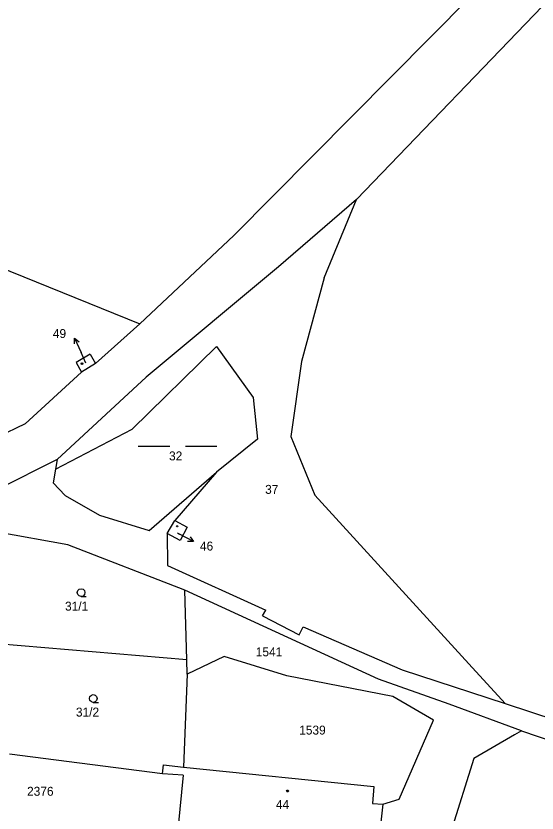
# Model space of a CAD drawing. Extents: x -852001 to -842497, y -1063614 to -1052182.
# Drawn here: x -850582.4 to -850483.1, y -1053481.6 to -1053329.6 of the extents above; entities that cross this region are included whole.
import ezdxf

# ---------------------------------------------------------------- set-up
doc = ezdxf.new("R2010")
doc.units = 0
for name, color, linetype in [('Default', 7, 'Continuous'), ('KN_HRANICE', 7, 'Continuous'), ('KN_KULTURY', 7, 'Continuous'), ('KN_PARCELY', 7, 'Continuous')]:
    doc.layers.add(name, color=color, linetype=linetype)

# ---------------------------------------------------------------- blocks, each defined once
blk = doc.blocks.new('304')
at = {"layer": 'Default'}
blk.add_lwpolyline([(0, 0), (-0.38, 0.1), (-0.65, 0.37), (-0.75, 0.74), (-0.65, 1.11), (-0.38, 1.38), (-0.01, 1.48), (0.36, 1.38), (0.63, 1.11), (0.73, 0.73), (0.63, 0.35), (0.36, 0.08), (-0.02, -0.02), (0.98, -0.02)], dxfattribs=at)
blk = doc.blocks.new('803')
at = {"layer": 'Default'}
for p, q in [((-7.5, 0), (-1.5, 0)), ((1.5, 0), (7.5, 0))]:
    blk.add_line(p, q, dxfattribs=at)
blk = doc.blocks.new('10292')
at = {"layer": 'Default'}
blk.add_line((0, 3), (0, 0), dxfattribs=at)
blk.add_lwpolyline([(-0.5, 2), (0, 3), (0.5, 2)], dxfattribs=at)
blk = doc.blocks.new('402')
at = {"layer": 'Default'}
blk.add_lwpolyline([(0.09, 0.15), (0.18, 0), (0.09, -0.15), (-0.09, -0.15), (-0.18, 0), (-0.09, 0.15), (0.09, 0.15)], dxfattribs=at)

msp = doc.modelspace()

# ---------------------------------------------------------------- linework, layer by layer
at = {"layer": 'KN_HRANICE'}
for p, q in [((-850422.36, -1053251.92), (-850540.88, -1053371.46)), ((-850471.08, -1053316.39), (-850517.5, -1053364.63)), ((-850517.5, -1053364.63), (-850532.35, -1053377.48)), ((-850523.63, -1053379.54), (-850517.5, -1053364.63)), ((-850540.88, -1053371.46), (-850558.84, -1053388.31)), ((-850593.21, -1053374.4), (-850558.84, -1053388.31)), ((-850532.35, -1053377.48), (-850557.63, -1053398.49)), ((-850523.63, -1053379.54), (-850527.95, -1053395.53)), ((-850558.84, -1053388.31), (-850567.28, -1053395.9)), ((-850560.27, -1053408.43), (-850544.19, -1053392.62)), ((-850544.19, -1053392.62), (-850537.17, -1053402.39)), ((-850568.31, -1053394.11), (-850570.95, -1053395.69)), ((-850568.31, -1053394.11), (-850567.28, -1053395.9)), ((-850570.95, -1053395.69), (-850569.94, -1053397.53)), ((-850567.28, -1053395.9), (-850569.94, -1053397.53)), ((-850527.95, -1053395.53), (-850530.04, -1053409.8)), ((-850569.94, -1053397.53), (-850580.7, -1053407.38)), ((-850557.63, -1053398.49), (-850574.57, -1053414.22)), ((-850537.17, -1053402.39), (-850536.37, -1053410.3)), ((-850580.7, -1053407.38), (-850599.94, -1053416.73)), ((-850574.9, -1053416.03), (-850560.27, -1053408.43)), ((-850536.37, -1053410.3), (-850544.21, -1053416.61)), ((-850530.04, -1053409.8), (-850525.46, -1053421.02)), ((-850574.57, -1053414.22), (-850604.96, -1053429.4)), ((-850574.57, -1053414.22), (-850574.9, -1053416.03)), ((-850574.9, -1053416.03), (-850575.37, -1053418.66)), ((-850557.06, -1053427.7), (-850544.21, -1053416.61)), ((-850544.21, -1053416.61), (-850552.11, -1053425.85)), ((-850575.37, -1053418.66), (-850573.02, -1053421.04)), ((-850573.02, -1053421.04), (-850566.48, -1053424.79)), ((-850525.46, -1053421.02), (-850496.05, -1053453.17)), ((-850566.48, -1053424.79), (-850557.06, -1053427.7)), ((-850572.57, -1053430.44), (-850592.25, -1053426.9)), ((-850553.62, -1053428.28), (-850552.11, -1053425.85)), ((-850552.11, -1053425.85), (-850549.78, -1053427.12)), ((-850549.78, -1053427.12), (-850551.12, -1053429.62)), ((-850551.12, -1053429.62), (-850553.62, -1053428.28)), ((-850553.62, -1053428.28), (-850553.56, -1053434.38)), ((-850550.25, -1053439.12), (-850572.57, -1053430.44)), ((-850553.56, -1053434.38), (-850534.81, -1053442.92)), ((-850513.32, -1053456.08), (-850550.25, -1053439.12)), ((-850549.87, -1053452.39), (-850550.25, -1053439.12)), ((-850535.39, -1053444.01), (-850534.81, -1053442.92)), ((-850535.39, -1053444.01), (-850528.4, -1053447.62)), ((-850528.4, -1053447.62), (-850527.68, -1053446.11)), ((-850527.68, -1053446.11), (-850508.76, -1053454.28)), ((-850549.87, -1053452.39), (-850589.27, -1053449.03)), ((-850549.8, -1053455.11), (-850549.87, -1053452.39)), ((-850542.75, -1053451.78), (-850549.8, -1053455.11)), ((-850530.79, -1053455.44), (-850542.75, -1053451.78)), ((-850508.76, -1053454.28), (-850489.13, -1053460.73)), ((-850496.05, -1053453.17), (-850489.13, -1053460.73)), ((-850549.8, -1053455.11), (-850550.5, -1053472.85)), ((-850510.58, -1053459.38), (-850530.79, -1053455.44)), ((-850499.79, -1053460.85), (-850513.32, -1053456.08)), ((-850502.78, -1053463.9), (-850510.58, -1053459.38)), ((-850486.02, -1053465.93), (-850499.79, -1053460.85)), ((-850489.13, -1053460.73), (-850443.14, -1053475.85)), ((-850509.34, -1053478.96), (-850502.78, -1053463.9)), ((-850487.33, -1053466.69), (-850495.1, -1053471.21)), ((-850486.02, -1053465.93), (-850487.33, -1053466.69)), ((-850486.02, -1053465.93), (-850460.49, -1053474.58)), ((-850554.48, -1053474.15), (-850583.69, -1053470.39)), ((-850495.1, -1053471.21), (-850500.17, -1053487.31)), ((-850554.48, -1053474.15), (-850554.3, -1053472.43)), ((-850554.3, -1053472.43), (-850550.5, -1053472.85)), ((-850550.5, -1053472.85), (-850514.2, -1053476.51)), ((-850550.56, -1053474.4), (-850554.48, -1053474.15)), ((-850550.56, -1053474.4), (-850551.52, -1053484.07)), ((-850514.2, -1053476.51), (-850514.44, -1053479.78)), ((-850514.44, -1053479.78), (-850512.46, -1053479.93)), ((-850512.46, -1053479.93), (-850512.92, -1053483.93)), ((-850512.46, -1053479.93), (-850509.34, -1053478.96))]:
    msp.add_line(p, q, dxfattribs=at)
at = {"layer": 'KN_PARCELY'}
for p, q in [((-850569.11, -1053395.83), (-850570.03, -1053393.77)), ((-850551.63, -1053428.18), (-850551.22, -1053428.41))]:
    msp.add_line(p, q, dxfattribs=at)

# ---------------------------------------------------------------- block references
at = {"layer": 'KN_KULTURY'}
for name, p in [('402', (-850569.84, -1053395.92)), ('803', (-850551.62, -1053411.66)), ('304', (-850570, -1053440.3)), ('304', (-850567.68, -1053460.5)), ('402', (-850530.63, -1053477.41))]:
    msp.add_blockref(name, p, dxfattribs=at)
at = {"layer": 'KN_KULTURY', "xscale": 0.67, "yscale": 0.67}
msp.add_blockref('402', (-850551.67, -1053426.93), dxfattribs=at)
at = {"layer": 'KN_PARCELY'}
for p, rotation in [((-850570.03, -1053393.77), 24.006932), ((-850551.22, -1053428.41), -118.78476800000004)]:
    msp.add_blockref('10292', p, dxfattribs=dict(at, rotation=rotation))

# ---------------------------------------------------------------- texts
for s, height, p in [('49', 1.7, (-850575.4, -1053391.03)), ('49', 0.1, (-850569.2, -1053395.83)), ('32', 1.7, (-850553.24, -1053414.36)), ('37', 1.7, (-850534.92, -1053420.74)), ('46', 0.1, (-850551.73, -1053428.18)), ('46', 1.7, (-850547.35, -1053431.55)), ('31/1', 1.7, (-850573.08, -1053443)), ('1541', 1.7, (-850536.7, -1053451.72)), ('31/2', 1.7, (-850571, -1053463.2)), ('1539', 1.7, (-850528.42, -1053466.63)), ('2376', 1.7, (-850580.32, -1053478.3)), ('44', 1.7, (-850532.85, -1053480.8))]:
    msp.add_text(s, height=height, dxfattribs=at).set_placement(p)

doc.saveas('drawing.dxf')
